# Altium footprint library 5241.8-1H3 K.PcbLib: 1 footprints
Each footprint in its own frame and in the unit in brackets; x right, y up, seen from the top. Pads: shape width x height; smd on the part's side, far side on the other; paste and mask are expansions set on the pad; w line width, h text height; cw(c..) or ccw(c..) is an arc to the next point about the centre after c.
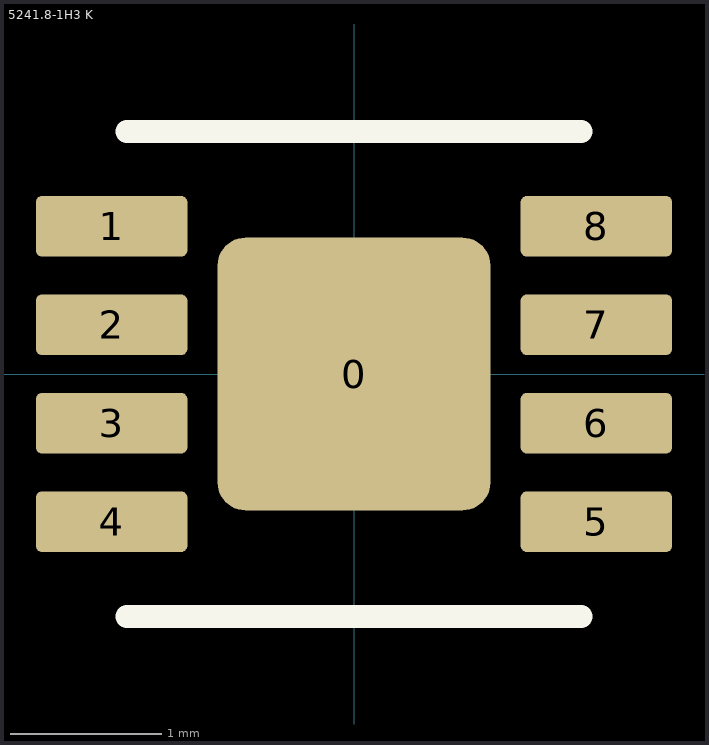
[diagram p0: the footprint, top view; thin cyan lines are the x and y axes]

## 5241.8-1H3 K [mm]
pads (9):
  rrect20% 1.8x1.8 smd mask+0: 0(0,0)
  rrect20% 1x0.4 smd mask+0: 1(-1.6,0.975) 2(-1.6,0.325) 3(-1.6,-0.325) 4(-1.6,-0.975) 5(1.6,-0.975) 6(1.6,-0.325) 7(1.6,0.325) 8(1.6,0.975)
Top Overlay:
  lines w0.15: -1.5,-1.6 1.5,-1.6 ; -1.5,1.6 1.5,1.6
  text "." at -2.52,1.385 h5
3D body "DFN-8-1EP_3x3mm_P0.65mm_EP1.55x2.4mm.step": height 0.77, standoff 0, extent -1.5,-1.49 1.5,1.49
